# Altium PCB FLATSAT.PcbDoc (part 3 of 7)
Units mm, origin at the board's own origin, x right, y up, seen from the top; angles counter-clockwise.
Board outline 430 x 350 mm, 5 copper layers (Top Layer, Internal Plane 1, Internal Plane 2, DELETEME, Bottom Layer); 808 components, 852 nets, 6407 pads, 939 vias.
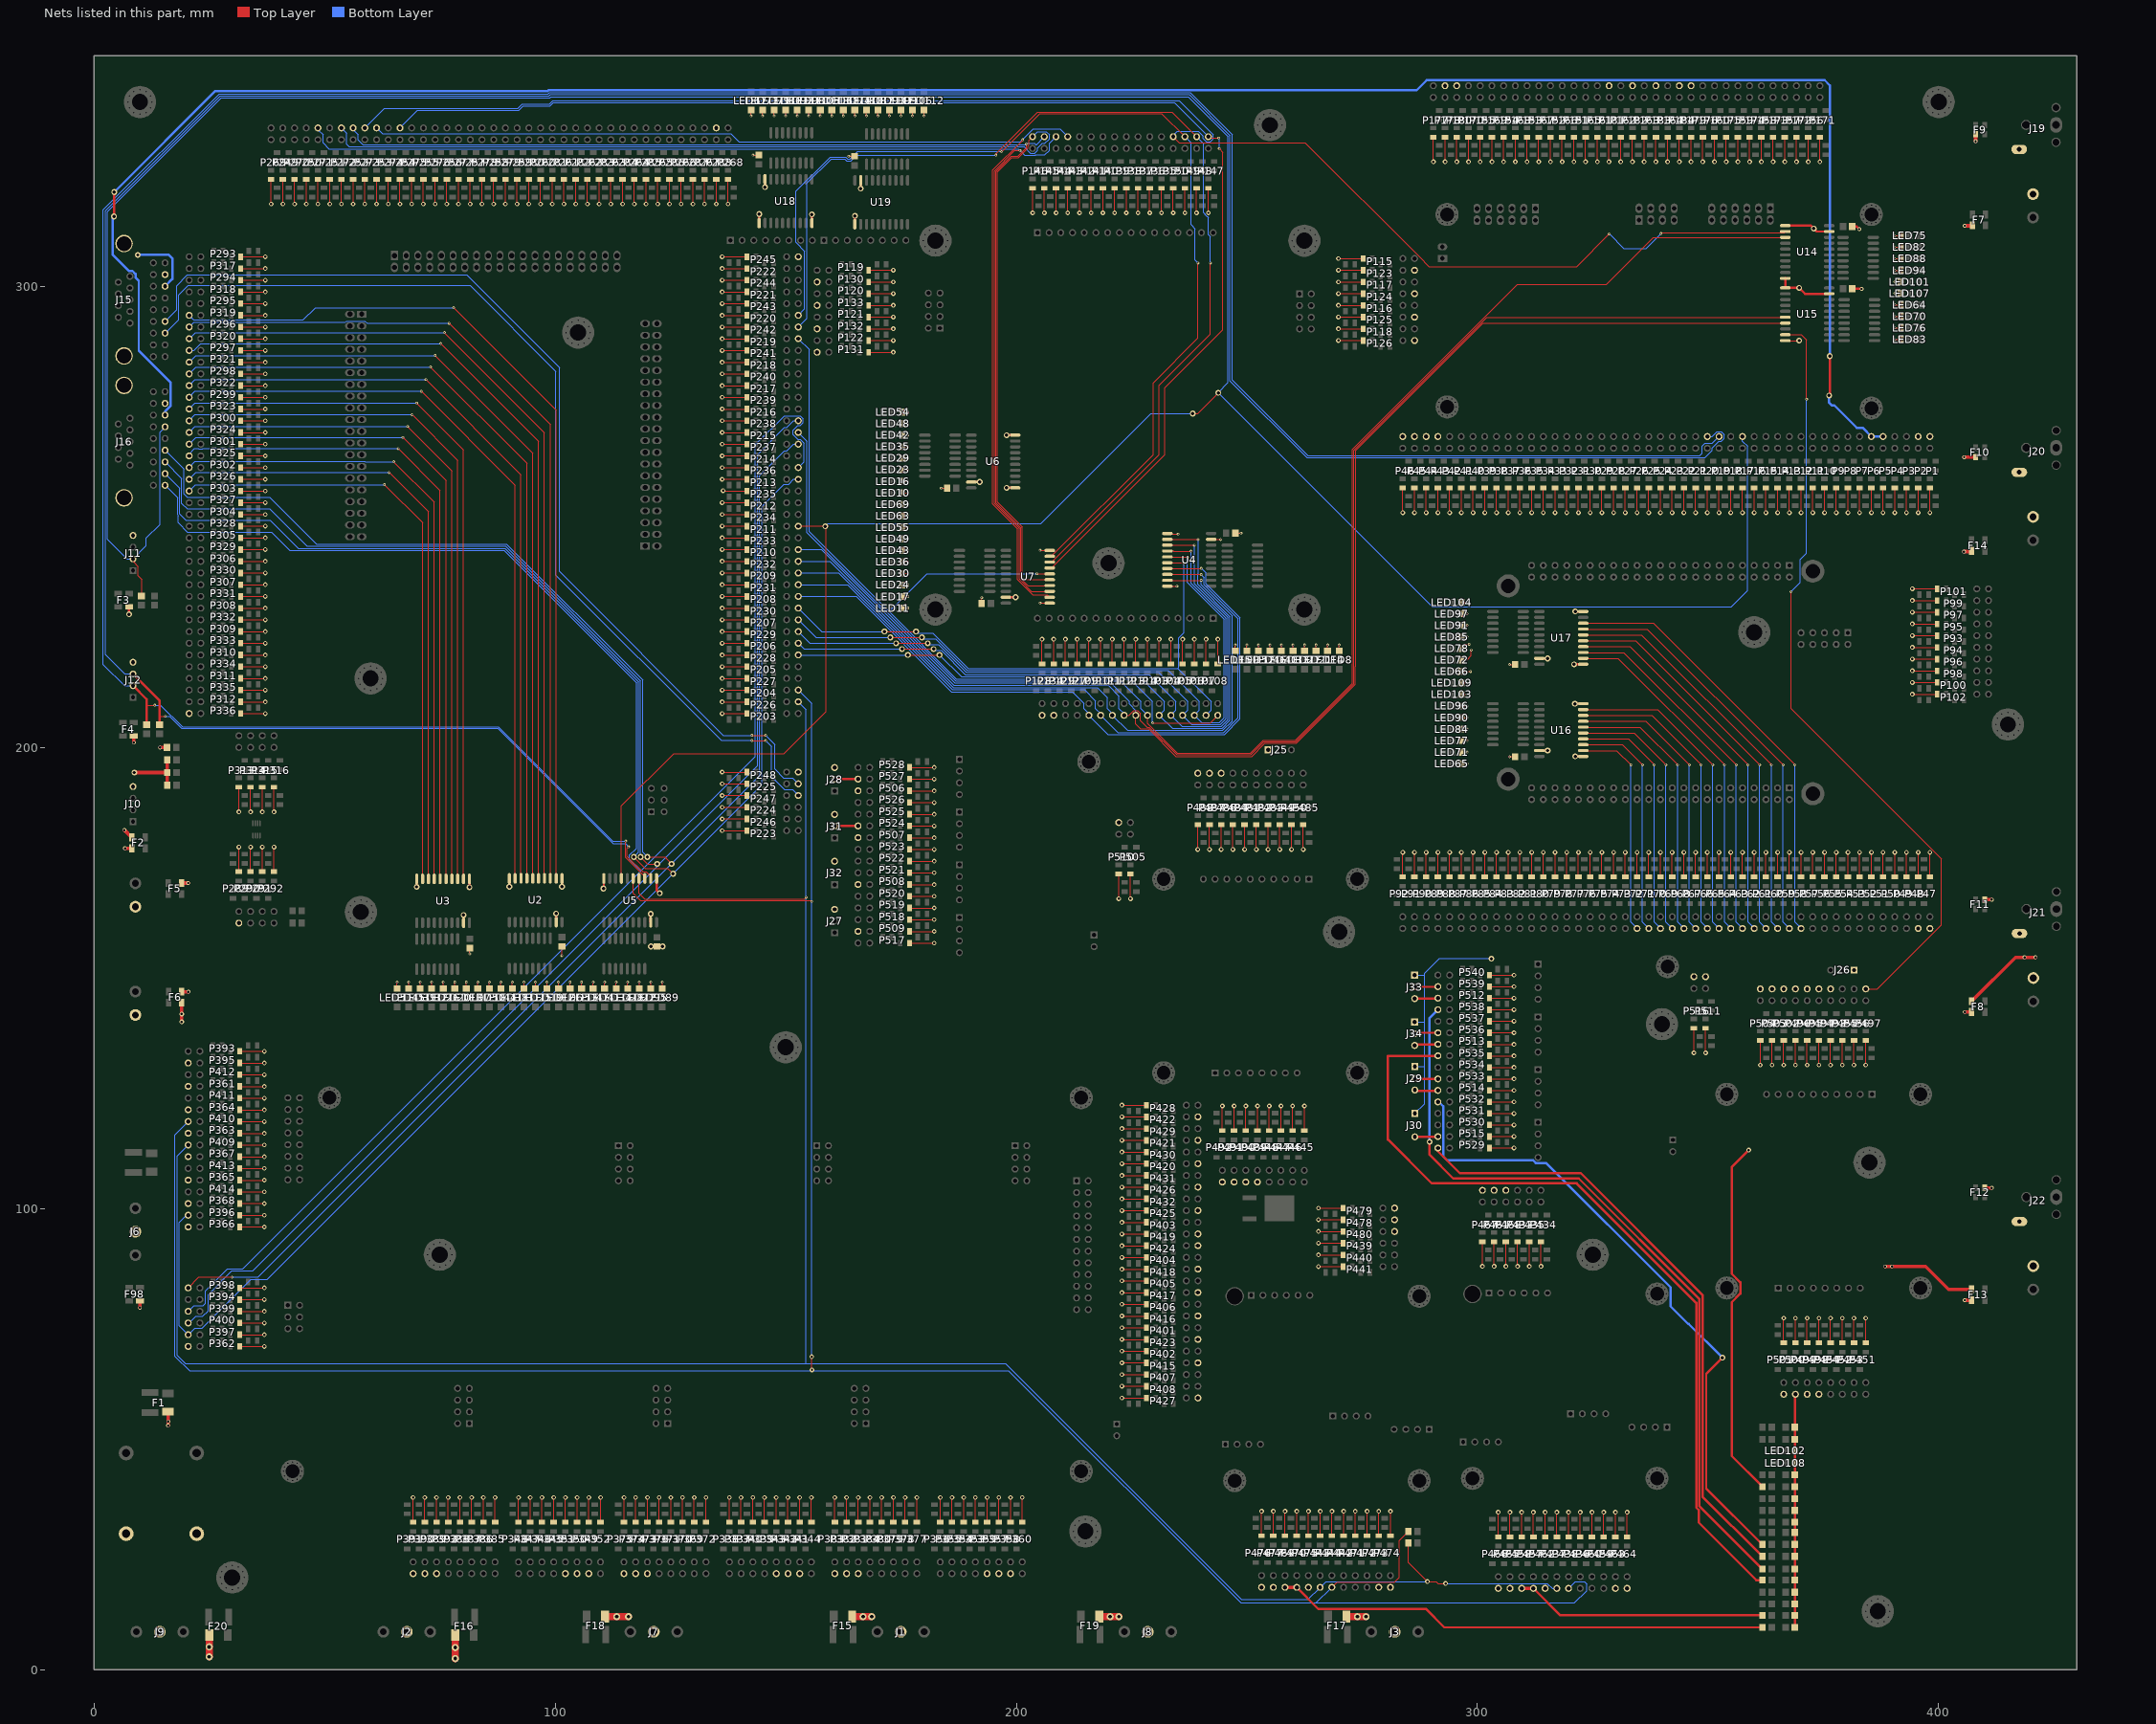
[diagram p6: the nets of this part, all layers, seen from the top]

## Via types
v1: diameter 1.016, hole 0.508, Top Layer to Bottom Layer, 541 vias
v2: diameter 0.6, hole 0.3, Top Layer to Bottom Layer, 214 vias
v3: diameter 1.27, hole 0.711, Top Layer to Bottom Layer, 147 vias
v4: diameter 0.8, hole 0.5, Top Layer to Bottom Layer, 31 vias
v5: diameter 0.5, hole 0.3, Top Layer to Bottom Layer, tented bottom, 5 vias
v6: diameter 1.27, hole 0.635, Top Layer to Bottom Layer, tented both sides, 1 vias

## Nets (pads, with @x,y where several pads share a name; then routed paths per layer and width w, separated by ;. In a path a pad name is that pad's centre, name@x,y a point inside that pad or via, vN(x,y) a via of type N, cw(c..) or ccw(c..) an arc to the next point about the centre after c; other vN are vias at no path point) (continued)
5V0_AUX: F6.1 P535.1 R23.2 | length 181.5
  Top Layer w0.508: P535.1@291.418,133.14 280.603,133.14 280.603,114.985 290.103,105.485 321.503,105.485 347.431,79.557 347.431,35.167 347.946,34.653 347.946,31.942 360.443,19.445 R23.2@361.803,19.445
  Top Layer w0.762: v1(19.049,140.507) v1(19.049,142.21) F6.1@19.049,144.686
5V0_AUX_E\N\: J34.2 P536.1 | length 5
  Top Layer w0.508: J34.2@286.458,138.14 P536.1@291.418,138.14
5V0_BBONE: P5.1 P6.1 P199.1 P538.1 R22.2 | length 689.1
  Top Layer w0.508: v3(4.369,315.189) 4.42,315.239 v3(4.42,320.472) ; v3(289.603,114.485) 289.603,111.685 294.742,106.546 321.942,106.546 348.117,80.371 348.117,35.451 361.703,21.865 R22.2@361.803,21.865 ; v3(376.224,276.352) 376.378,276.505 v3@376.378,284.886 ; v3(376.403,284.886) v3@376.403,285.096
  Bottom Layer w0.508: v3(4.369,315.189) 4.1,314.92 4.1,306.85 7.564,303.386 8.326,303.386 9.026,302.686 9.026,301.924 9.728,301.222 9.728,286.072 16.65,279.15 16.65,274.136 15.443,272.928 P199.1@15.443,272.096 ; v3(4.42,320.472) 26.326,342.378 98.346,342.378 98.545,342.577 286.814,342.577 288.974,344.737 375.277,344.737 376.4,343.614 376.4,287.3 ; v3(289.603,114.485) 289.603,141.325 P538.1@291.418,143.14 ; v3(376.224,276.352) 376.174,276.302 376.174,274.858 376.814,274.218 377.353,274.218 382.229,269.342 383.501,269.342 P6.1@385.398,267.445 P5.1@387.938,267.445 ; v3(376.403,284.886) v3@376.403,285.096 ; v3(376.403,284.886) 376.403,287.25
5V0_BCR: P395.1 P532.1 R20.2 | length 140.5
  Top Layer w0.508: v3(353.103,67.685) 349.603,64.185 349.603,39.285 361.703,27.185 R20.2@361.803,27.185
  Bottom Layer w0.508: P532.1@291.418,123.14 291.648,123.14 292.603,122.185 292.603,111.285 293.403,110.485 312.08,110.485 312.654,109.91 314.878,109.91 341.859,82.929 341.859,78.829 345.703,74.985 345.803,74.985 v3(353.103,67.685)
5V0_TELEM: F2.1 P190.1 P529.1 R9.1 R10.1 R11.1 R21.2 | length 162.5
  Top Layer w0.508: P529.1@291.418,113.14 291.418,112.462 296.203,107.677 322.411,107.677 348.803,81.285 348.803,37.505 361.703,24.605 R21.2@361.803,24.605
  Top Layer w0.762: v4(6.6,182.1) 8.2,180.5 F2.1@8.25,180.5 ; v3(8.778,194.579) R10.1@15.904,194.579 ; R9.1@15.904,191.829 R10.1@15.904,194.579 ; R11.1@15.904,197.329 R10.1@15.904,194.579
  Bottom Layer w0.508: v3(9.525,306.832) 16.256,306.832 17.018,306.07 17.018,301.611 P190.1@15.443,300.036
5V0_UNREG: J29.1 J30.1 J33.1 J34.1 P493.1 P494.1 P495.1 P496.1 P511.1 R15.2 | length 132.5
  Top Layer w0.508: v1(358.803,112.685) 355.103,108.985 355.103,85.889 356.991,84.001 356.991,81.572 355.103,79.684 355.103,46.385 R15.2@361.803,39.685
  Bottom Layer w0.254: J34.1@286.389,140.47 288.488,140.47 288.503,140.485 ; J33.1@286.389,150.63 288.503,150.63 ; J30.1@286.418,120.64 288.503,122.725 288.503,130.8 ; J29.1@286.418,130.8 288.503,130.8 ; v3(303.022,154.178) 303.022,154.305 291.719,154.305 288.503,151.089 288.503,150.63 ; 288.503,130.8 288.503,140.485 ; 288.503,140.485 288.503,150.63
5V0_UNREG_PG: P497.1 U15.9 | length 169.2
  Top Layer w0.152: U15.9@366.75,289.52 370.23,289.52 371.35,288.4 v2(371.35,275.55) ; v2@367.975,233.925 v2(367.975,233.8) 367.975,208.425 398.363,178.037 398.414,178.037 400.6,175.851 400.6,161.55 386.702,147.652 P497.1@384.184,147.652
  Bottom Layer w0.152: v2(367.975,233.8) 369.944,235.769 369.944,240.782 371.35,242.188 v2(371.35,275.55)
8V0_RX1: F8.1 P457.1 P458.1 R24.2 | length 72.4
  Top Layer w0.508: P457.1@312.127,17.64 317.981,11.785 R24.2@361.803,11.785
  Top Layer w0.762: P458.1@309.587,17.64 P457.1@312.127,17.64 ; F8.1@407.15,145 416.65,154.5 v4(421,154.5)
  other v4: 418.6,154.5
8V0_RX2: F13.1 P469.1 P470.1 R26.2 | length 128
  Top Layer w0.508: P470.1@260.811,17.874 265.5,13.185 266.559,13.185 266.576,13.202 288.786,13.202 292.803,9.185 361.783,9.185 R26.2@361.803,9.165
  Top Layer w0.762: P469.1@258.271,17.874 P470.1@260.811,17.874 ; v4(388.374,87.472) v4(389.882,87.472) 397.182,87.472 402.154,82.5 F13.1@407.15,82.5
AFSK1_DET: P108.1 P219.1 U7.6 | length 190.2
  Top Layer w0.152: v2(204.475,237.675) 204.48,237.67 U7.6@207.25,237.67
  Top Layer w0.254: v2(229.575,205.35) 242.048,205.35 P108.1@243.69,206.992
  Bottom Layer w0.152: 172.425,229.5 180.6,237.675 v2(204.475,237.675)
  Bottom Layer w0.254: P219.1@152.734,288.654 155.104,286.284 155.104,246.822 172.425,229.5 187.029,214.896 224.614,214.896 229.531,209.98 229.531,205.394 v2(229.575,205.35)
AFSK1_M0: P144.1 P271.1 U7.3 | length 272.2
  Top Layer w0.152: v2(200.8,329.5) 199.666,329.5 195.24,325.074 195.24,252.926 200.64,247.526 200.64,236.526 200.736,236.43 200.833,236.333 203.306,233.86 U7.3@207.25,233.86
  Bottom Layer w0.254: P271.1@48.594,334.374 48.594,333.994 49.674,332.914 49.674,331.146 50.981,329.839 200.461,329.839 v2(200.8,329.5) 201.858,328.441 204.158,328.441 204.24,328.524 206.206,328.524 207.163,329.481 207.163,331.008 P144.1@208.622,332.468
AFSK1_M1: P145.1 P252.1 U7.4 | length 260.7
  Top Layer w0.152: 201.067,236.567 202.503,235.13 U7.4@207.25,235.13 ; 201.067,236.567 200.97,236.663 200.97,247.663 195.57,253.063 195.57,324.937 198.863,328.23 200.33,328.23 202.2,330.1 v2(202.2,330.9)
  Bottom Layer w0.254: P252.1@56.214,334.374 56.214,333.994 57.294,332.914 57.294,331.766 58.307,330.754 202.054,330.754 202.308,331.008 203.99,331.008 204.244,330.754 204.368,330.754 P145.1@206.082,332.468 P145.1@205.569,332.468
AFSK1_RXD: P143.1 P253.1 U7.2 | length 261.8
  Top Layer w0.152: v2(201.4,331.8) 201.4,331.701 194.909,325.21 194.909,252.79 200.309,247.39 200.309,236.39 200.406,236.293 200.503,236.196 200.6,236.1 203.591,233.108 206.732,233.108 U7.2@207.25,232.59
  Bottom Layer w0.254: P253.1@61.294,334.374 62.56,333.108 138.137,333.108 139.915,331.33 200.876,331.33 203.67,334.124 209.507,334.124 P143.1@211.162,332.468
AFSK1_TXD: P146.1 P272.1 U7.5 | length 272.1
  Top Layer w0.152: P146.1@203.542,332.468 202.754,331.68 202.754,330.671 202.53,330.447 202.53,329.963 200.467,327.9 199,327.9 195.9,324.8 195.9,253.2 201.3,247.8 201.3,236.8 201.7,236.4 U7.5@207.25,236.4
  Bottom Layer w0.254: P272.1@53.674,334.374 54.825,333.223 54.825,330.822 55.35,330.297 201.682,330.297 203.106,328.873 203.979,328.873 204.061,328.955 204.097,328.955 204.623,329.481 204.623,329.998 205.701,331.076 206.218,331.076 207.163,332.021 207.163,332.916 206.53,333.548 204.623,333.548 P146.1@203.542,332.468
AFSK2_DET: P114.1 P215.1 U14.3 | length 332.4
  Top Layer w0.152: P114.1@228.45,206.992 228.45,205.205 234.9,198.755 250.78,198.755 253.599,201.574 260.502,201.574 272.87,213.942 272.87,264.611 308.716,300.457 327.924,300.457 338.107,310.64 U14.3@366.75,310.64
  Bottom Layer w0.254: P215.1@152.734,268.334 154.647,266.421 154.647,246.632 186.84,214.439 222.531,214.439 226.991,209.98 226.991,208.452 P114.1@228.45,206.992
AFSK2_M0: P148.1 P242.1 U7.8 | length 233.8
  Top Layer w0.152: v2(195.6,328.5) 195.6,328.8 204.63,337.83 233.74,337.83 P148.1@239.102,332.468 ; U7.8@207.25,240.21 207.634,240.21 230.97,263.546 230.97,278.566 242.092,289.688 v2(242.092,305.1)
  Bottom Layer w0.152: P148.1@239.102,332.468 240.638,330.932 240.638,315.961 240.88,315.719 240.88,315.642 241.327,315.196 241.403,315.196 241.681,314.919 241.681,311.242 242.092,310.83 v2(242.092,305.1)
  Bottom Layer w0.254: P242.1@152.734,291.194 154.596,293.056 154.596,322.389 159.867,327.66 162.804,327.66 163.251,327.213 164.109,327.213 165.396,328.5 v2(195.6,328.5)
AFSK2_M1: P149.1 P220.1 U7.9 | length 227.9
  Top Layer w0.152: v2(196.8,329.2) 205.1,337.5 231.531,337.5 P149.1@236.562,332.468 ; U7.9@207.25,241.48 207.634,241.48 229.7,263.546 229.7,279.092 239.4,288.792 v2(239.4,305.1)
  Bottom Layer w0.152: P149.1@236.562,332.468 237.9,331.131 237.9,313.37 238.8,312.47 238.8,305.7 v2(239.4,305.1)
  Bottom Layer w0.254: P220.1@152.734,293.734 154.139,295.139 154.139,307.61 152.185,309.563 152.185,320.625 159.652,328.092 162.983,328.092 163.429,327.645 163.931,327.645 165.56,329.275 v2@196.875,329.275
AFSK2_RXD: P147.1 P254.1 U7.7 | length 292.4
  Top Layer w0.152: U7.7@207.25,238.94 207.634,238.94 232.24,263.546 232.24,278.04 244.785,290.585 244.785,329.115 v2(244,329.9) ; P147.1@241.642,332.468 241.911,332.2 v2(243.9,332.2)
  Bottom Layer w0.152: v2(243.9,332.2) 244,332.1 v2(244,329.9)
  Bottom Layer w0.254: P254.1@66.374,334.374 70.197,338.197 92.149,338.197 93.079,339.127 98.939,339.127 99.671,339.859 234.252,339.859 P147.1@241.642,332.468
AFSK2_TXD: P150.1 P273.1 U14.2 | length 351.3
  Top Layer w0.152: P150.1@234.022,332.468 235.316,331.175 262.659,331.175 287.366,306.468 287.366,306.434 289.475,304.325 321.5,304.325 v2(328.575,311.4) ; v2(339.8,311.475) 340,311.675 366.515,311.675 U14.2@366.75,311.91
  Bottom Layer w0.152: v2(328.575,311.4) 331.7,308.275 336.6,308.275 v2(339.8,311.475)
  Bottom Layer w0.254: P273.1@58.754,334.374 63.035,338.655 91.96,338.655 92.89,339.585 98.786,339.585 99.492,340.291 235.347,340.291 242.723,332.916 242.723,332.021 242.09,331.388 241.195,331.388 240.499,332.084 240.499,332.6 239.483,333.616 234.911,333.616 234.022,332.727 P150.1@234.022,332.468
BB_DEBUG_0: P72.1 U16.2 | length 47.8
  Top Layer w0.152: U16.2@322.75,199.34 330.16,199.34 v2(333.25,196.25)
  Bottom Layer w0.152: v2(333.25,196.25) 333.25,162.113 P72.1@334.598,160.765
BB_DEBUG_1: P71.1 U16.3 | length 50.9
  Top Layer w0.152: U16.3@322.75,200.61 331.43,200.61 v2(335.79,196.25)
  Bottom Layer w0.152: v2(335.79,196.25) 335.79,162.113 P71.1@337.138,160.765
BB_DEBUG_2: P70.1 U16.4 | length 54
  Top Layer w0.152: U16.4@322.75,201.88 332.7,201.88 v2(338.33,196.25)
  Bottom Layer w0.152: v2(338.33,196.25) 338.33,162.113 P70.1@339.678,160.765
BB_DEBUG_3: P69.1 U16.5 | length 57
  Top Layer w0.152: U16.5@322.75,203.15 333.97,203.15 v2(340.87,196.25)
  Bottom Layer w0.152: v2(340.87,196.25) 340.87,162.113 P69.1@342.218,160.765
BB_DEBUG_4: P68.1 U16.6 | length 60.1
  Top Layer w0.152: U16.6@322.75,204.42 335.24,204.42 v2(343.41,196.25)
  Bottom Layer w0.152: v2(343.41,196.25) 343.41,162.113 P68.1@344.758,160.765
BB_DEBUG_5: P67.1 U16.7 | length 63.2
  Top Layer w0.152: U16.7@322.75,205.69 336.51,205.69 v2(345.95,196.25)
  Bottom Layer w0.152: v2(345.95,196.25) 345.95,162.113 P67.1@347.298,160.765
BB_DEBUG_6: P66.1 U16.8 | length 66.2
  Top Layer w0.152: U16.8@322.75,206.96 337.78,206.96 v2(348.49,196.25)
  Bottom Layer w0.152: v2(348.49,196.25) 348.49,162.113 P66.1@349.838,160.765
BB_DEBUG_7: P65.1 U16.9 | length 69.3
  Top Layer w0.152: U16.9@322.75,208.23 339.05,208.23 v2(351.03,196.25)
  Bottom Layer w0.152: v2(351.03,196.25) 351.03,162.113 P65.1@352.378,160.765
BB_DEBUG_8: P64.1 U17.2 | length 76.4
  Top Layer w0.152: U17.2@322.75,219.34 330.48,219.34 v2(353.57,196.25)
  Bottom Layer w0.152: v2(353.57,196.25) 353.57,162.113 P64.1@354.918,160.765
BB_DEBUG_9: P63.1 U17.3 | length 79.5
  Top Layer w0.152: U17.3@322.75,220.61 331.75,220.61 v2(356.11,196.25)
  Bottom Layer w0.152: v2(356.11,196.25) 356.11,162.113 P63.1@357.458,160.765
BB_DEBUG_10: P62.1 U17.4 | length 82.6
  Top Layer w0.152: U17.4@322.75,221.88 333.02,221.88 v2(358.65,196.25)
  Bottom Layer w0.152: v2(358.65,196.25) 358.65,162.113 P62.1@359.998,160.765
BB_DEBUG_11: P61.1 U17.5 | length 85.6
  Top Layer w0.152: U17.5@322.75,223.15 334.29,223.15 v2(361.19,196.25)
  Bottom Layer w0.152: v2(361.19,196.25) 361.19,162.113 P61.1@362.538,160.765
BB_DEBUG_12: P60.1 U17.6 | length 88.7
  Top Layer w0.152: U17.6@322.75,224.42 335.56,224.42 v2(363.73,196.25)
  Bottom Layer w0.152: v2(363.73,196.25) 363.73,162.113 P60.1@365.078,160.765
BB_DEBUG_13: P59.1 U17.7 | length 91.8
  Top Layer w0.152: U17.7@322.75,225.69 336.83,225.69 v2(366.27,196.25)
  Bottom Layer w0.152: v2(366.27,196.25) 366.27,162.113 P59.1@367.618,160.765
BB_DEBUG_14: P58.1 U17.8 | length 94.8
  Top Layer w0.152: U17.8@322.75,226.96 338.1,226.96 v2(368.81,196.25)
  Bottom Layer w0.152: v2(368.81,196.25) 368.81,162.113 P58.1@370.158,160.765
BBONE_E\N\: J33.2 P539.1 | length 5
  Top Layer w0.508: J33.2@286.418,148.1 P539.1@291.378,148.1
BBONE_I2C2_SCL: J12.2 P19.1 R2.2 U5.3 | length 669.8
  Top Layer w0.152: 11.43,209.169 v2(13.208,209.169) ; v2(115.316,179.705) 115.316,176.131 119.463,171.984 U5.3@119.463,171.6
  Top Layer w0.508: J12.2@8.5,213.42 11.43,210.49 11.43,209.169 R2.2@11.43,204.962
  Bottom Layer w0.152: v2(13.208,209.169) 14.478,209.169 19.177,204.47 87.716,204.47 112.481,179.705 v2(115.316,179.705)
  Bottom Layer w0.254: J12.2@8.5,213.42 6.629,213.42 2.032,218.017 2.032,316.595 27.205,341.768 98.526,341.768 98.776,342.018 237.721,342.018 246.812,332.927 246.812,279.679 263.195,263.296 348.183,263.296 348.758,263.871 348.758,265.352 349.391,265.985 350.872,265.985 352.332,267.445 P19.1@352.378,267.445
BBONE_I2C2_SDA: J12.3 P20.1 R1.2 U5.2 | length 672.9
  Top Layer w0.152: 14.224,206.756 v2(15.494,206.756) ; v2(115.951,178.486) 115.646,178.181 115.646,176.416 118.98,173.082 119.78,173.082 120.733,172.129 U5.2@120.733,171.6
  Top Layer w0.508: J12.3@8.5,215.96 14.224,210.236 14.224,206.756 R1.2@14.224,204.962
  Bottom Layer w0.152: v2(15.494,206.756) 16.424,206.756 19.04,204.14 87.579,204.14 112.568,179.151 115.286,179.151 v2(115.951,178.486)
  Bottom Layer w0.254: J12.3@8.5,215.96 6.629,215.96 2.489,220.1 2.489,316.406 27.42,341.336 98.705,341.336 98.955,341.586 237.506,341.586 246.355,332.738 246.355,279.49 263.005,262.839 349.3,262.839 350.918,264.458 350.918,264.973 352.31,266.365 352.825,266.365 353.458,266.998 353.458,267.892 352.825,268.525 351.931,268.525 350.85,267.445 P20.1@349.838,267.445
BCR_E\N\: J29.2 P533.1 | length 5
  Top Layer w0.508: J29.2@286.418,128.1 P533.1@291.378,128.1
BCR_MISO: P196.1 P237.1 P398.1 | length 418.2
  Top Layer w0.254: P398.1@20.451,82.812 22.763,85.125 v2(29.95,85.125) ; v3(120.015,176.251) 123.749,176.251 v3(125.24,174.76)
  Bottom Layer w0.254: P196.1@15.443,264.476 19.5,260.418 19.5,255 20.25,254.25 38.125,254.25 48.256,244.119 89.494,244.119 118.999,214.614 118.999,177.267 v3(120.015,176.251) ; v2@29.925,85.16 35.64,85.16 v3(125.24,174.76) 144.352,193.872 144.352,258.94 149.747,264.334 150.298,264.334 151.758,265.794 P237.1@152.734,265.794
BCR_MOSI: P197.1 P238.1 P400.1 | length 423.2
  Top Layer w0.254: v3(118.542,176.251) 120.04,174.752 v3(122.149,174.752)
  Bottom Layer w0.254: P197.1@15.443,261.936 19.049,258.329 19.049,252.951 20.25,251.75 38.088,251.75 46.176,243.662 89.304,243.662 118.542,214.425 v3(118.542,176.251) ; P400.1@20.451,75.192 20.717,75.192 22.15,76.625 23.575,76.625 24.781,77.831 24.781,81.353 29.904,86.475 34.466,86.475 122.149,174.158 v3@122.149,174.333 ; v3(122.149,174.752) 122.567,174.752 143.895,196.079 143.895,263.562 149.747,269.414 150.298,269.414 151.758,270.874 P238.1@152.734,270.874
BCR_R\S\T\: P194.1 P213.1 P396.1 P397.1 | length 445.3
  Top Layer w0.254: v3(117.069,176.251) 119.534,173.785 124.459,173.785 v3(125.602,172.642)
  Bottom Layer w0.254: P194.1@15.443,259.396 18.618,256.221 18.568,256.221 18.568,250.682 20,249.25 38.25,249.25 44.295,243.205 89.115,243.205 118.085,214.235 118.085,177.267 v3(117.069,176.251) ; P396.1@20.451,98.56 20.084,98.56 18.52,96.996 18.52,74.583 P397.1@20.451,72.652 21.911,74.112 23.438,74.112 34.029,84.703 37.598,84.703 144.86,191.965 144.86,252.292 149.662,257.094 150.641,257.094 151.722,258.174 P213.1@152.734,258.174
BCR_SCK: P195.1 P236.1 P399.1 | length 434.4
  Bottom Layer w0.254: P195.1@15.443,256.856 18.136,254.162 18.136,250.389 18.25,250.276 18.25,248.75 20.25,246.75 38.5,246.75 42.502,242.748 88.925,242.748 117.627,214.046 117.627,178.174 116.103,176.65 116.103,175.747 118.625,173.225 ; P399.1@20.451,77.732 21.668,78.95 23.7,78.95 24.225,79.475 24.225,82.132 29,86.907 32.307,86.907 118.625,173.225 ; 150.045,271.955 150.044,271.954 149.747,271.954 143.438,265.645 143.438,198.038 118.625,173.225 ; 150.046,271.954 153.181,271.954 153.814,271.321 153.814,270.427 153.181,269.794 152.666,269.794 151.654,268.781 151.654,267.887 152.666,266.874 153.181,266.874 154.004,266.052 154.004,261.984 P236.1@152.734,260.714
COMMS_E\N\: J28.2 P527.1 | length 5.1
  Top Layer w0.508: J28.2@160.608,193.15 P527.1@165.688,193.15
CSC_E\N\: J31.2 P524.1 | length 5.1
  Top Layer w0.508: J31.2@160.608,182.99 P524.1@165.688,182.99
CSC_ISP: P188.1 P247.1 | length 220.3
  Top Layer w0.254: v2@142.689,201.51 v2(145.669,201.51)
  Bottom Layer w0.254: P188.1@15.443,289.876 18.386,292.819 18.386,298.136 20.5,300.25 81.532,300.25 100.185,281.597 100.185,237.381 136.039,201.527 v2(142.672,201.527) ; v2(145.669,201.51) 146.939,200.24 146.939,193.65 149.733,190.856 151.472,190.856 P247.1@152.734,189.594
CSC_RST: P187.1 P225.1 | length 219.3
  Top Layer w0.254: v2(142.672,202.659) v2@145.652,202.659
  Bottom Layer w0.254: P187.1@15.443,292.416 17.955,294.928 17.955,300.146 20.308,302.5 80.882,302.5 100.985,282.397 100.985,238.181 136.508,202.659 v2(142.672,202.659) ; v2(145.669,202.641) 147.625,200.685 147.625,195.326 149.555,193.396 151.472,193.396 P225.1@152.734,192.134
DEBUG_0: P303.1 U3.9 | length 131.8
  Top Layer w0.152: v2(63,257) 71.27,248.73 U3.9@71.27,171.5
  Bottom Layer w0.254: P303.1@20.654,255.634 22.02,257 v2(63,257)
DEBUG_1: P326.1 U3.8 | length 135.7
  Top Layer w0.152: v2(64,259.659) 72.54,251.119 U3.8@72.54,171.5
  Bottom Layer w0.254: P326.1@20.654,258.174 22.139,259.659 v2(64,259.659)
DEBUG_2: P302.1 U3.7 | length 139
  Top Layer w0.152: v2(65,262) 73.81,253.19 U3.7@73.81,171.5
  Bottom Layer w0.254: P302.1@20.654,260.714 21.959,262.019 58.801,262.019 58.819,262 v2(65,262)
DEBUG_3: P325.1 U3.6 | length 143.4
  Top Layer w0.152: v2@66,264.825 75.08,255.745 U3.6@75.08,171.5
  Bottom Layer w0.254: P325.1@20.654,263.254 20.654,263.654 21.825,264.825 22.671,264.825 22.757,264.739 23.631,264.739 23.717,264.825 v2(66,264.825)
DEBUG_4: P301.1 U3.5 | length 146.6
  Top Layer w0.152: v2(67,267.25) 76.35,257.9 U3.5@76.35,171.5
  Bottom Layer w0.254: P301.1@20.654,265.794 22.11,267.25 v2(67,267.25)
DEBUG_5: P324.1 U3.4 | length 150
  Top Layer w0.152: v2(68,269.639) 77.62,260.019 U3.4@77.62,171.5
  Bottom Layer w0.254: P324.1@20.654,268.334 21.959,269.639 v2(68,269.639)
DEBUG_6: P300.1 U3.3 | length 153.7
  Top Layer w0.152: v2(69,272.179) 78.89,262.289 U3.3@78.89,171.5
  Bottom Layer w0.254: P300.1@20.654,270.874 21.959,272.179 v2(69,272.179)
DEBUG_7: P323.1 U3.2 | length 157.3
  Top Layer w0.152: v2(70,274.719) 80.16,264.559 U3.2@80.16,171.5
  Bottom Layer w0.254: P323.1@20.654,273.414 21.959,274.719 v2(70,274.719)
DEBUG_8: P299.1 U2.9 | length 164.9
  Top Layer w0.152: v2(71,277.259) 91.345,256.914 U2.9@91.345,171.625
  Bottom Layer w0.254: P299.1@20.654,275.954 21.959,277.259 v2(71,277.259)
DEBUG_9: P322.1 U2.8 | length 168.6
  Top Layer w0.152: v2(72,279.799) 92.615,259.184 U2.8@92.615,171.625
  Bottom Layer w0.254: P322.1@20.654,278.494 21.959,279.799 v2(72,279.799)
DEBUG_10: P298.1 U2.7 | length 172.5
  Top Layer w0.152: v2(73,282.519) 93.885,261.634 U2.7@93.885,171.625
  Bottom Layer w0.254: P298.1@20.654,281.034 22.139,282.519 v2(73,282.519)
DEBUG_11: P321.1 U2.6 | length 176.1
  Top Layer w0.152: v2(74,285) 95.155,263.845 U2.6@95.155,171.625
  Bottom Layer w0.254: P321.1@20.654,283.574 22.08,285 v2(74,285)
DEBUG_12: P297.1 U2.5 | length 179.9
  Top Layer w0.152: v2(75.225,287.599) 96.425,266.399 U2.5@96.425,171.625
  Bottom Layer w0.254: P297.1@20.654,286.114 21.702,286.114 23.187,287.599 v2(75.225,287.599)
DEBUG_13: P320.1 U2.4 | length 183.3
  Top Layer w0.152: v2(76,290) 97.695,268.305 U2.4@97.695,171.625
  Bottom Layer w0.254: P320.1@20.654,288.654 22,290 v2(76,290)
DEBUG_14: P296.1 U2.3 | length 186.6
  Top Layer w0.152: v2(77,292) 98.965,270.035 U2.3@98.965,171.625
  Bottom Layer w0.254: P296.1@20.654,291.194 21.709,292.249 54.53,292.249 54.78,292.499 58.801,292.499 59.299,292 v2(77,292)
DEBUG_15: P319.1 U2.2 | length 191.8
  Top Layer w0.152: v2(78,295.375) 100.235,273.14 U2.2@100.235,171.625
  Bottom Layer w0.152: P319.1@20.654,293.734 21.658,292.73 37.738,292.73
  Bottom Layer w0.254: 37.738,292.73 45.38,292.73 48.025,295.375 77.625,295.375 v2(78,295.375)
DTMF1Q1: P103.1 P228.1 U4.2 | length 153.4
  Top Layer w0.254: v3(176.491,220.078) v3(183.349,220.078) v3@183.603,219.824 ; U4.2@232.75,245.16 234.049,245.16 234.109,245.1 v2(239.425,245.1)
  Bottom Layer w0.254: P228.1@152.734,220.074 176.487,220.074 v3(176.491,220.078) ; v3(183.349,220.078) 188.073,215.353 226.697,215.353 232.071,209.98 232.071,208.072 P103.1@230.99,206.992 233.837,204.145 244.613,204.145 246.37,205.902 246.37,228.394 239.418,235.346 239.418,237.636 ; 239.425,237.642 v2(239.425,245.1)
DTMF1Q2: P104.1 P206.1 U4.3 | length 151.3
  Top Layer w0.254: v3(175.221,221.348) v3(182.079,221.348) ; U4.3@232.75,243.89 234.049,243.89 234.064,243.875 v2(238.625,243.875)
  Bottom Layer w0.254: P206.1@152.734,222.614 154,221.348 v3(175.221,221.348) ; v3(182.079,221.348) 182.383,221.043 183.748,221.043 188.981,215.81 228.78,215.81 234.611,209.98 234.611,208.072 P104.1@233.53,206.992 235.945,204.577 244.435,204.577 245.939,206.081 245.939,228.215 238.625,235.529 v2(238.625,243.875)
DTMF1Q3: P105.1 P229.1 U4.4 | length 149.9
  Top Layer w0.254: v3(173.951,222.618) v3(180.809,222.618) ; U4.4@232.75,242.62 234.049,242.62 234.069,242.6 v2(237.9,242.6)
  Bottom Layer w0.254: P229.1@152.734,225.154 155.27,222.618 v3(173.951,222.618) 174.063,222.618 v3@174.235,222.446 ; v3(180.809,222.618) 181.113,222.313 183.125,222.313 189.17,216.268 230.863,216.268 237.151,209.98 237.151,208.072 P105.1@236.07,206.992 238.054,205.009 244.256,205.009 245.507,206.26 245.507,228.036 237.9,235.643 v2(237.9,242.6)
DTMF1Q4: P106.1 P207.1 U4.5 | length 148
  Top Layer w0.254: v3(172.681,223.888) v3(179.539,223.888) ; U4.5@232.75,241.35 237,241.35 v2(237.1,241.25)
  Bottom Layer w0.254: P207.1@152.734,227.694 156.54,223.888 v3(172.681,223.888) v3@172.935,223.888 ; v3(179.539,223.888) 179.843,223.583 182.502,223.583 189.36,216.725 232.945,216.725 239.691,209.98 239.691,208.072 P106.1@238.61,206.992 240.162,205.441 244.077,205.441 245.075,206.439 245.075,227.857 237.1,235.832 v2(237.1,241.25)
DTMF1ST: P107.1 P230.1 U4.6 | length 128.5
  Top Layer w0.254: v3(171.411,225.158) v3(178.269,225.158) ; U4.6@232.75,240.08 236.17,240.08 v2(236.325,239.925)
  Bottom Layer w0.254: P230.1@152.734,230.234 157.81,225.158 v3(171.411,225.158) v3@171.665,225.158 ; v3(178.269,225.158) 178.573,224.853 181.878,224.853 189.549,217.182 235.028,217.182 ; v2(236.325,239.925) 236.325,224.873 235.767,224.315 235.734,224.315 235.2,223.781 235.2,217.354 235.028,217.182 ; P107.1@241.15,206.992 242.231,208.072 242.231,209.98 235.028,217.182
DTMF2Q1: P109.1 P208.1 U4.7 | length 153.9
  Top Layer w0.254: U4.7@232.75,238.81 240.06,238.81 v2(240.1,238.85)
  Bottom Layer w0.254: P208.1@152.734,232.774 165.272,232.774 185.944,212.102 212.168,212.102 214.67,209.6 214.67,208.452 215.75,207.372 P109.1@215.75,206.992 219.893,202.85 245.15,202.85 248.537,206.237 248.537,228.138 241.175,235.5 241.175,237.875 v2@240.2,238.85
DTMF2Q2: P110.1 P231.1 U4.8 | length 152.9
  Top Layer w0.254: U4.8@232.75,237.54 240.06,237.54 v2(240.1,237.5)
  Bottom Layer w0.254: P231.1@152.734,235.314 163.379,235.314 186.133,212.559 214.743,212.559 217.21,210.092 217.21,208.452 218.29,207.372 P110.1@218.29,206.992 222.001,203.282 244.971,203.282 248.105,206.415 248.105,227.881 240.743,235.242 240.743,236.857 v2(240.1,237.5)
DTMF2Q3: P111.1 P209.1 U4.9 | length 151.4
  Top Layer w0.254: U4.9@232.75,236.27 234.049,236.27 234.054,236.275 v2(240.1,236.275)
  Bottom Layer w0.254: P209.1@152.734,237.854 161.485,237.854 186.323,213.016 217.588,213.016 219.75,210.854 219.75,208.452 220.83,207.372 P111.1@220.83,206.992 224.109,203.714 244.792,203.714 246.802,205.724 246.802,228.573 240.1,235.275 240.1,236.1 240.188,236.188 v2@240.275,236.275
DTMF2Q4: P112.1 P232.1 U15.6 | length 304
  Top Layer w0.152: P112.1@223.37,206.992 224.419,206.992 225.474,208.047 226.347,208.047 226.965,207.429 226.965,205.81 228.375,204.4 228.788,204.4 234.763,198.425 250.917,198.425 253.736,201.244 260.639,201.244 273.2,213.805 273.2,264.474 302.056,293.33 U15.6@366.75,293.33
  Bottom Layer w0.254: P232.1@152.734,240.394 159.592,240.394 186.512,213.474 219.925,213.474 222.29,211.108 222.29,208.452 223.37,207.372 P112.1@223.37,206.992
DTMF2ST: P113.1 P210.1 U15.7 | length 303.2
  Top Layer w0.152: P113.1@225.91,206.992 225.91,205.065 226.905,204.07 228.651,204.07 234.627,198.095 251.054,198.095 253.873,200.914 260.776,200.914 273.53,213.668 273.53,217.57 273.632,217.671 273.632,264.439 301.253,292.06 U15.7@366.75,292.06
  Bottom Layer w0.254: P210.1@152.734,242.934 157.698,242.934 186.651,213.982 220.449,213.982 224.497,209.934 224.497,209.41 225.91,207.996 P113.1@225.91,206.992
GND: C1.1 C2.1 C3.1 C4.1 C5.1 C6.1 C7.1 C8.1 C9.1 C10.1 C11.1 C12.1 C13.1 F1.3 F2.3 F3.3 F4.3 F5.3 F6.3 F7.3 F8.3 F9.3 F10.3 F11.3 F12.3 F13.3 F14.3 F15.3 F16.3 F17.3 F18.3 F19.3 F20.3 F98.3 J1.2 J2.2 J3.2 J5.1 J6.2 J7.2 J8.2 J9.2 J10.4 J11.4 J12.4 J13.2 J14.2 J15.10 J15.11 J16.10 J16.11 J17.2 J18.2 J19.1 J20.1 J21.1 J22.1 J23.2 J24.2 J25.1 J26.1 J27.3 J28.3 J29.3 J30.3 J31.3 J32.3 J33.3 J34.3 LED1.2 LED2.2 LED3.2 LED4.2 LED5.2 LED6.1 LED7.1 LED8.1 LED9.1 LED10.1 LED11.1 LED12.1 LED13.1 LED14.1 LED15.1 LED16.1 LED17.1 LED18.2 LED19.1 LED20.1 LED21.1 LED22.1 LED23.1 LED24.1 LED25.1 LED26.1 LED27.1 LED28.1 LED29.1 LED30.1 LED31.1 LED32.1 LED33.1 LED34.1 LED35.1 LED36.1 LED37.2 LED38.1 LED39.1 LED40.1 LED41.1 LED42.1 LED43.1 LED44.1 LED45.1 LED46.1 LED47.1 LED48.1 LED49.1 LED50.1 LED51.1 LED52.1 LED53.1 LED54.1 LED55.1 LED56.2 LED57.2 LED58.2 LED59.2 LED60.2 LED61.2 LED62.2 LED63.1 LED64.1 LED65.1 LED66.1 LED67.1 LED68.1 LED69.1 LED70.1 LED71.1 LED72.1 LED73.1 LED74.1 LED75.1 LED76.1 LED77.1 LED78.1 LED79.1 LED80.1 LED81.2 LED82.1 LED83.1 LED84.1 LED85.1 LED86.1 LED87.1 LED88.1 LED89.1 LED90.1 LED91.1 LED92.1 LED93.1 LED94.1 LED95.1 LED96.1 LED97.1 LED98.1 LED99.1 LED100.2 LED101.1 LED102.1 LED103.1 LED104.1 LED105.1 LED106.1 LED107.1 LED108.1 LED109.1 LED111.1 LED112.1 P1.1 P1.3 P2.1 P2.3 P3.3 P4.3 P5.3 P6.3 P7.3 P8.3 P9.3 P10.3 P11.3 P12.3 P13.3 P14.3 P15.3 P16.3 P17.3 P18.3 P19.3 P20.3 P21.3 P22.3 P23.3 P24.3 P25.3 P26.3 P27.3 P28.3 P29.3 P30.3 P31.3 P32.3 P33.3 P34.3 P35.3 P36.3 P37.3 P38.3 P39.3 P40.3 P41.3 P42.3 P43.1 P43.3 P44.1 P44.3 P45.1 P45.3 P46.1 P46.3 P47.1 P47.3 P48.1 P48.3 P49.3 P50.3 P51.3 P52.3 P53.3 P54.3 P55.3 P56.3 P57.3 P58.3 P59.3 P60.3 P61.3 P62.3 P63.3 P64.3 P65.3 P66.3 P67.3 P68.3 P69.3 P70.3 P71.3 P72.3 P73.3 P74.3 P75.3 P76.3 P77.3 P78.3 P79.3 P80.3 P81.3 P82.3 P83.3 P84.3 P85.3 P86.3 P87.3 P88.3 P89.3 P90.3 P91.3 P92.3 P93.3 P94.3 P95.3 P96.3 P97.3 P98.3 P99.3 P100.3 P101.3 P102.3 P103.3 P104.3 P105.3 P106.3 P107.3 P108.3 P109.3 P110.3 P111.3 P112.3 P113.3 P114.3 P115.3 P116.3 P117.3 P118.3 P119.3 P120.3 P121.3 P122.3 P123.1 P123.3 P124.1 P124.3 P125.1 P125.3 P126.1 P126.3 P127.3 P128.1 P128.3 P129.3 P130.1 P130.3 P131.1 P131.3 P132.1 P132.3 P133.1 P133.3 P134.1 P134.3 P135.3 P136.3 P137.3 P138.3 P139.3 P140.3 P141.3 P142.3 P143.3 P144.3 P145.3 P146.3 P147.3 P148.3 P149.3 P150.3 P151.3 P152.3 P153.3 P154.3 P155.3 P156.3 P157.3 P158.3 P159.3 P160.3 P161.3 P162.3 P163.3 P164.3 P165.3 P166.3 P167.3 P168.3 P169.3 P170.3 P171.3 P172.3 P173.3 P174.3 P175.3 P176.3 P177.3 P178.1 P178.3 P179.1 P179.3 P180.1 P180.3 P181.1 P181.3 P182.1 P182.3 P183.1 P183.3 P184.1 P184.3 P193.1 P202.1 P203.3 P204.3 P205.3 P206.3 P207.3 P208.3 P209.3 P210.3 P211.3 P212.3 P213.3 P214.3 P215.3 P216.3 P217.3 P218.3 P219.3 P220.3 P221.3 P222.3 P223.3 P224.3 P225.3 P226.3 P227.3 P228.3 P229.3 P230.3 P231.3 P232.3 P233.3 P234.3 P235.3 P236.3 P237.3 P238.3 P239.3 P240.3 P241.3 P242.3 P243.3 P244.3 P245.1 P245.3 P246.3 P247.3 P248.1 P248.3 P249.3 P250.3 P251.3 P252.3 P253.3 P254.3 P255.3 P256.3 P257.3 P258.3 P259.3 P260.3 P261.3 P262.3 P263.3 P264.3 P265.3 P266.3 P267.3 P268.3 P269.3 P270.3 P271.3 P272.3 P273.3 P274.3 P275.3 P276.3 P277.3 P278.3 P279.3 P280.3 P281.3 P282.3 P283.3 P284.3 P285.3 P286.3 P287.3 P288.1 P288.3 P289.1 P289.3 P290.3 P291.3 P292.3 P293.3 P294.3 P295.3 P296.3 P297.3 P298.3 P299.3 P300.3 P301.3 P302.3 P303.3 P304.3 P305.3 P306.3 P307.3 P308.3 P309.3 P310.3 P311.3 P312.3 P313.3 P314.3 P315.3 P316.3 P317.3 P318.3 P319.3 P320.3 P321.3 P322.3 P323.3 P324.3 P325.3 P326.3 P327.3 P328.3 P329.3 P330.3 P331.3 P332.3 P333.3 P334.3 P335.3 P336.1 P336.3 P337.3 P338.3 P339.3 P340.3 P341.1 P341.3 P342.1 P342.3 P343.1 P343.3 P344.3 P345.3 P346.3 P347.3 P348.3 P349.1 P349.3 P350.1 P350.3 P351.1 P351.3 P352.3 P353.3 P354.3 P355.3 P356.3 P357.1 P357.3 P358.1 P358.3 P359.1 P359.3 P360.3 P361.1 P361.3 P362.1 P362.3 P363.1 P363.3 P364.1 P364.3 P365.1 P365.3 P366.1 P366.3 P367.1 P367.3 P368.1 P368.3 P369.3 P370.3 P371.3 P372.3 P373.1 P373.3 P374.1 P374.3 P375.1 P375.3 P376.3 P377.3 P378.3 P379.3 P380.3 P381.1 P381.3 P382.1 P382.3 P383.1 P383.3 P384.3 P385.3 P386.3 P387.3 P388.3 P389.1 P389.3 P390.1 P390.3 P391.1 P391.3 P392.3 P393.3 P394.3 P395.3 P396.3 P397.3 P398.3 P399.3 P400.3 P401.3 P402.3 P403.3 P404.3 P405.3 P406.3 P407.3 P408.3 P409.3 P410.3 P411.3 P412.3 P413.3 P414.3 P415.1 P415.3 P416.1 P416.3 P417.1 P417.3 P418.1 P418.3 P419.1 P419.3 P420.1 P420.3 P421.1 P421.3 P422.1 P422.3 P423.1 P423.3 P424.1 P424.3 P425.1 P425.3 P426.1 P426.3 P427.1 P427.3 P428.3 P429.3 P430.3 P431.3 P432.3 P433.3 P434.3 P435.3 P436.3 P437.3 P438.3 P439.3 P440.3 P441.3 P442.3 P443.3 P444.3 P445.3 P446.3 P447.3 P448.3 P449.3 P450.3 P451.3 P452.3 P453.3 P454.3 P455.3 P456.3 P457.3 P458.3 P459.3 P460.3 P461.1 P461.3 P462.1 P462.3 P463.1 P463.3 P464.1 P464.3 P465.1 P465.3 P466.1 P466.3 P467.1 P467.3 P468.1 P468.3 P469.3 P470.3 P471.3 P472.3 P473.1 P473.3 P474.1 P474.3 P475.1 P475.3 P476.1 P476.3 P477.1 P477.3 P478.1 P478.3 P479.1 P479.3 P480.1 P480.3 P481.3 P482.3 P483.3 P484.3 P485.3 P486.1 P486.3 P487.1 P487.3 P488.1 P488.3 P489.1 P489.3 P490.1 P490.3 P491.1 P491.3 P492.1 P492.3 P493.3 P494.3 P495.3 P496.3 P497.3 P498.1 P498.3 P499.1 P499.3 P500.1 P500.3 P501.1 P501.3 P502.1 P502.3 P503.1 P503.3 P504.1 P504.3 P505.3 P506.1 P506.3 P507.1 P507.3 P508.1 P508.3 P509.1 P509.3 P510.1 P510.3 P511.3 P512.1 P512.3 P513.1 P513.3 P514.1 P514.3 P515.1 P515.3 P516.1 P516.3 P517.3 P518.3 P519.3 P520.3 P521.3 P522.3 P523.3 P524.3 P525.3 P526.3 P527.3 P528.3 P529.3 P530.3 P531.3 P532.3 P533.3 P534.3 P535.3 P536.3 P537.3 P538.3 P539.3 P540.3 pad.0 pad.1 U2.1 U2.10 U2.19 U3.1 U3.10 U3.19 U4.1 U4.10 U4.19 U5.1 U5.10 U5.19 U6.1 U6.10 U6.19 U7.1 U7.10 U7.19 U14.1 U14.10 U14.19 U15.1 U15.10 U15.19 U16.1 U16.10 U16.19 U17.1 U17.10 U17.19 U18.1 U18.10 U18.19 U19.1 U19.19 | length 345.1
  Top Layer w0.152: LED51.1@65.75,147.75 v2@65.75,149 ; LED45.1@68.25,147.75 v2@68.25,149 ; LED39.1@70.75,147.75 v2@70.75,149 ; LED32.1@73.25,147.75 v2@73.25,149 ; LED26.1@75.75,147.75 v2@75.75,149 ; LED20.1@78.25,147.75 v2@78.25,149 ; LED13.1@80.75,147.75 v2@80.75,149 ; v2(81.5,155.25) C3.1@81.5,156.5 ; LED7.1@83.25,147.75 v2@83.25,149 ; LED50.1@85.75,147.75 v2@85.75,149 ; LED44.1@88.25,147.75 v2@88.25,149 ; LED38.1@90.75,147.75 v2@90.75,149 ; LED31.1@93.25,147.75 v2@93.25,149 ; LED25.1@95.75,147.75 v2@95.75,149 ; LED19.1@98.25,147.75 v2@98.25,149 ; LED12.1@100.75,147.75 v2@100.75,149 ; v2(101.472,154.862) 101.505,154.895 C2.1@101.505,156.875 ; LED6.1@103.25,147.75 v2@103.25,149 ; LED53.1@105.75,147.75 v2@105.75,149 ; LED47.1@108.25,147.75 v2@108.25,149 ; LED41.1@110.75,147.75 v2@110.75,149 ; LED34.1@113.25,147.75 v2@113.25,149 ; LED28.1@115.75,147.75 v2@115.75,149 ; LED22.1@118.25,147.75 v2@118.25,149 ; LED95.1@120.75,147.75 v2@120.75,149 ; LED89.1@123.25,147.75 v2@123.25,149 ; v2(142.5,337) LED67.1@142.5,338.25 ; v2(142.93,328.5) C12.1@144.18,328.5 ; v2(145,337) LED73.1@145,338.25 ; v2(147.5,337) LED79.1@147.5,338.25 ; v2(150,337) LED86.1@150,338.25 ; v2(152.5,337) LED92.1@152.5,338.25 ; v2(155,337) LED98.1@155,338.25 ; v2(157.5,337) LED105.1@157.5,338.25 ; v2(160,337) LED111.1@160,338.25 ; v2(162.5,337) LED68.1@162.5,338.25 ; v2(163.68,328.25) C13.1@164.93,328.25 ; v2(165,337) LED74.1@165,338.25 ; v2(167.5,337) LED80.1@167.5,338.25 ; v2(170,337) LED87.1@170,338.25 ; v2(172.5,337) LED93.1@172.5,338.25 ; v2(175,337) LED99.1@175,338.25 ; LED11.1@175.25,230.25 v2(176.5,230.25) ; LED17.1@175.25,232.75 v2(176.5,232.75) ; LED24.1@175.25,235.25 v2(176.5,235.25) ; LED30.1@175.25,237.75 v2(176.5,237.75) ; LED36.1@175.25,240.25 v2(176.5,240.25) ; LED43.1@175.25,242.75 v2(176.5,242.75) ; LED49.1@175.25,245.25 v2(176.5,245.25) ; LED55.1@175.25,247.75 v2(176.5,247.75) ; LED63.1@175.25,250.25 v2(176.5,250.25) ; LED69.1@175.25,252.75 v2(176.5,252.75) ; LED10.1@175.25,255.25 v2(176.5,255.25) ; LED16.1@175.25,257.75 v2(176.5,257.75) ; LED23.1@175.25,260.25 v2(176.5,260.25) ; LED29.1@175.25,262.75 v2(176.5,262.75) ; LED35.1@175.25,265.25 v2(176.5,265.25) ; LED42.1@175.25,267.75 v2(176.5,267.75) ; LED48.1@175.25,270.25 v2(176.5,270.25) ; LED54.1@175.25,272.75 v2(176.5,272.75) ; v2(177.5,337) LED106.1@177.5,338.25 ; v2(180,337) LED112.1@180,338.25 ; v2(183.75,256.25) C6.1@185,256.25 ; C7.1@192.5,231.25 v2(192.5,232.5) ; v2(205.15,231.345) 205.175,231.32 U7.1@207.25,231.32 ; v2(205.15,242.775) 205.175,242.75 U7.10@207.25,242.75 ; U4.10@232.75,235 234.825,235 v2(234.85,234.975) ; U4.1@232.75,246.43 232.88,246.3 v2(235.1,246.3) ; U4.19@242.25,245.16 244.29,245.16 v2(244.325,245.125) ; LED15.1@247.5,221 v2(247.5,222.25) ; C4.1@247.5,246.5 v2(248.75,246.5) ; LED9.1@250,221 v2(250,222.25) ; LED52.1@252.5,221 v2(252.5,222.25) ; LED46.1@255,221 v2(255,222.25) ; LED40.1@257.5,221 v2(257.5,222.25) ; LED33.1@260,221 v2(260,222.25) ; LED27.1@262.5,221 v2(262.5,222.25) ; LED21.1@265,221 v2(265,222.25) ; LED14.1@267.5,221 v2(267.5,222.25) ; LED8.1@270,221 v2(270,222.25) ; LED65.1@296.5,196.5 v2(297.75,196.5) ; LED71.1@296.5,199 v2(297.75,199) ; LED77.1@296.5,201.5 v2(297.75,201.5) ; LED84.1@296.5,204 v2(297.75,204) ; LED90.1@296.5,206.5 v2(297.75,206.5) ; LED96.1@296.5,209 v2(297.75,209) ; LED103.1@296.5,211.5 v2(297.75,211.5) ; LED109.1@296.5,214 v2(297.75,214) ; LED66.1@296.5,216.5 v2(298.5,216.5) ; LED72.1@296.5,219 297.75,219 298.658,219.908 v2(298.658,221.161) ; LED78.1@296.5,221.5 297.4,222.4 v2(298.2,222.4) ; LED85.1@296.5,224 v2(297.75,224) ; LED91.1@296.5,226.5 v2(297.75,226.5) ; LED97.1@296.5,229 v2(297.75,229) ; LED104.1@296.5,231.5 v2(297.75,231.5) ; v2(306.921,198) C10.1@308.171,198 ; v2(306.921,218) C11.1@308.171,218 ; v2(390.5,288.5) LED83.1@391.75,288.5 ; v2(390.5,291) LED76.1@391.75,291 ; v2(390.5,293.5) LED70.1@391.75,293.5 ; v2(390.5,296) LED64.1@391.75,296 ; v2(390.5,298.5) LED107.1@391.75,298.5 ; v2(390.5,301) LED101.1@391.75,301 ; v2(390.5,303.5) LED94.1@391.75,303.5 ; v2(390.5,306) LED88.1@391.75,306 ; v2(390.5,308.5) LED82.1@391.75,308.5 ; v2(390.5,311) LED75.1@391.75,311
  Top Layer w0.254: v1@136.224,255.634 136.295,255.705 v1(136.414,255.705) ; U15.10@366.75,288.25 v3(369.75,288.25)
  Top Layer w0.508: v3(7.62,228.905) F3.3@7.62,230.502 ; v3(70,169.776) U3.10@70,171.5 ; U3.19@80.16,162 v3(80.16,163.68) ; v3(81.43,169.695) U3.1@81.43,171.5 ; v3(90.075,169.831) U2.10@90.075,171.625 ; U2.19@100.235,162.125 v3(100.235,163.989) ; v3(101.505,169.831) U2.1@101.505,171.625 ; v3(110.49,169.418) 110.573,169.501 U5.10@110.573,171.6 ; U5.19@120.733,162.1 v3(120.733,163.913) ; v3(120.782,156.85) C5.1@122.073,156.85 v3(123.322,156.85) ; U5.1@122.003,171.6 122.003,169.081 v3(122.682,168.402) ; U18.1@144.25,313.75 v3(144.25,315.7) ; v3(145.52,321.542) U18.19@145.52,323.25 ; U18.10@155.68,313.75 v3(155.68,315.617) ; U19.1@165,313.5 v3(165,315.314) ; v3(166.27,321.21) U19.19@166.27,323 ; U6.19@190.25,257.59 v3(192.058,257.59) ; U7.19@197.75,232.59 v3(199.845,232.59) ; v3(197.9,256.32) U6.1@199.75,256.32 ; v3(197.9,267.75) U6.10@199.75,267.75 ; J30.3@286.418,115.56 P515.1@291.338,115.56 ; J29.3@286.418,125.56 P514.1@291.338,125.56 ; J34.3@286.418,135.56 P513.1@291.338,135.56 ; J33.3@286.418,145.56 P512.1@291.338,145.56 ; U16.19@313.421,199.34 v3(315.214,199.34) ; U17.19@313.421,219.34 v3@315.214,219.34 ; v3@320.929,218.07 U17.1@322.921,218.07 ; v3(321.133,209.5) U16.10@322.921,209.5 ; v3(321.183,198.07) U16.1@322.921,198.07 ; v3(321.194,229.5) U17.10@322.921,229.5 ; U14.10@366.75,301.75 U15.1@366.75,299.68 v3(369.75,299.68) 371.02,298.41 U15.19@376.25,298.41 ; U14.1@366.75,313.18 372.287,313.18 v3(372.92,312.547) 373.557,311.91 U14.19@376.25,311.91 ; LED81.2@368.803,9.165 LED61.2@368.803,11.785 LED100.2@368.803,14.245 LED62.2@368.803,16.825 LED60.2@368.803,19.445 LED59.2@368.803,21.865 LED58.2@368.803,24.605 LED57.2@368.803,27.185 LED56.2@368.803,29.765 LED37.2@368.803,32.025 LED18.2@368.803,34.525 LED5.2@368.803,37.105 LED4.2@368.803,39.685 LED3.2@368.803,42.265 LED2.2@368.803,49.965 LED1.2@368.803,52.585 368.803,59.595 P500.1@368.944,59.736 ; C8.1@381.25,313 382.198,313 v4(382.778,312.42) ; C9.1@381.284,299.466 v4(383.286,299.466)
  Top Layer w0.762: v4(6.741,178.15) F2.3@8.25,178.15 ; v4(8.667,201.051) F4.3@8.667,202.56 ; v4(10,78.5) F98.3@10,80 ; v4(14.361,199.994) C1.1@15.87,199.994 ; v4(16.097,52.94) F1.3@16.097,55.94 ; F5.3@19,170.6 v4(20.451,170.6) ; F6.3@19.049,147.036 v4(20.5,147.036) ; v4(405.501,242.494) F14.3@407.01,242.494 ; v4(405.526,262.966) F10.3@407.772,262.966 ; v4(405.641,80.15) F13.3@407.15,80.15 ; v4(405.641,142.65) F8.3@407.15,142.65 ; v4(405.641,313.15) F7.3@407.15,313.15 ; v4(408,331.491) F9.3@408,333 ; F12.3@410,104.5 v4(411.509,104.5) ; F11.3@410,167 v4(411.509,167)
  Top Layer w1.524: pad.1@25.019,2.794 25.035,3.318 F20.3@25.035,7.53 ; pad.1@78.359,2.413 78.375,3.318 F16.3@78.375,7.53 ; F18.3@110.823,11.52 115.035,11.52 pad.1@115.926,11.506 ; F15.3@164.417,11.52 168.629,11.52 pad.1@168.645,11.504 ; F19.3@218.011,11.52 222.223,11.52 pad.1@222.239,11.504 ; F17.3@271.605,11.52 275.817,11.52 pad.1@275.833,11.504
  Bottom Layer w0.508: v3@122.555,168.529 v3(122.682,168.402)
  other v1: 304.507,34.15 307.047,34.15 309.587,34.15 312.127,34.15 314.667,34.15 317.207,34.15 319.747,34.15 322.287,34.15 324.827,34.15 327.367,34.15 329.907,34.15 332.447,34.15 253.191,34.384 255.731,34.384 258.271,34.384 260.811,34.384 263.351,34.384 265.891,34.384 268.431,34.384 270.971,34.384 273.511,34.384 276.051,34.384 278.591,34.384 281.131,34.384 69.219,37.346 71.759,37.346 74.299,37.346 76.839,37.346 79.379,37.346 81.919,37.346 84.459,37.346 86.999,37.346 92.079,37.346 94.619,37.346 97.159,37.346 99.699,37.346 102.239,37.346 104.779,37.346 107.319,37.346 109.859,37.346 114.939,37.346 117.479,37.346 120.019,37.346 122.559,37.346 125.099,37.346 127.639,37.346 130.179,37.346 132.719,37.346 137.799,37.346 140.339,37.346 142.879,37.346 145.419,37.346 147.959,37.346 150.499,37.346 153.039,37.346 155.579,37.346 160.659,37.346 163.199,37.346 165.739,37.346 168.279,37.346 170.819,37.346 173.359,37.346 175.899,37.346 178.439,37.346 183.519,37.346 186.059,37.346 188.599,37.346 191.139,37.346 193.679,37.346 196.219,37.346 198.759,37.346 201.299,37.346 222.889,58.936 222.889,61.476 222.889,64.016 222.889,66.556 222.889,69.096 36.961,70.112 222.889,71.636 36.961,72.652 222.889,74.176 36.961,75.192 366.404,76.246 368.944,76.246 371.484,76.246 374.024,76.246 376.564,76.246 379.104,76.246 381.644,76.246 384.184,76.246 222.889,76.716 36.961,77.732 222.889,79.256 36.961,80.272 222.889,81.796 36.961,82.812 222.889,84.336 222.889,86.876 265.524,87.423 301.07,87.47 303.61,87.47 306.15,87.47 308.69,87.47 311.23,87.47 313.77,87.47 222.889,89.416 265.524,89.963 222.889,91.956 265.524,92.503 222.889,94.496 265.524,95.043 36.961,96.02 222.889,97.036 265.524,97.583 36.961,98.56 222.889,99.576 265.524,100.123 36.961,101.1 222.889,102.116 36.961,103.64 222.889,104.656 36.961,106.18 222.889,107.196 36.961,108.72 222.889,109.736 36.961,111.26 222.889,112.276 307.928,113.14 36.961,113.8 222.889,114.816 307.928,115.64 36.961,116.34 222.889,117.356 307.928,118.14 36.961,118.88 222.889,119.896 307.928,120.64 36.961,121.42 244.682,122.268 247.222,122.268 249.762,122.268 252.302,122.268 254.842,122.268 257.382,122.268 259.922,122.268 262.462,122.268 222.889,122.436 307.928,123.14 36.961,123.96 307.928,125.64 36.961,126.5 307.928,128.14 36.961,129.04 307.928,130.64 361.324,131.142 363.864,131.142 366.404,131.142 368.944,131.142 371.484,131.142 374.024,131.142 376.564,131.142 379.104,131.142 381.644,131.142 384.184,131.142 36.961,131.58 307.928,133.14 346.92,133.783 349.46,133.783 36.961,134.12 307.928,135.64 307.928,138.14 307.928,140.64 307.928,143.14 307.928,145.64 307.928,148.14 307.928,150.64 182.198,157.59 182.198,160.13 182.198,162.67 182.198,165.21 222.219,167.226 224.759,167.226 182.198,167.75 182.198,170.29 182.198,172.83 182.198,175.37 283.798,177.275 286.338,177.275 288.878,177.275 291.418,177.275 293.958,177.275 296.498,177.275 299.038,177.275 301.578,177.275 304.118,177.275 306.658,177.275 309.198,177.275 311.738,177.275 314.278,177.275 316.818,177.275 319.358,177.275 321.898,177.275 324.438,177.275 326.978,177.275 329.518,177.275 332.058,177.275 334.598,177.275 337.138,177.275 339.678,177.275 342.218,177.275 344.758,177.275 347.298,177.275 349.838,177.275 352.378,177.275 354.918,177.275 357.458,177.275 359.998,177.275 362.538,177.275 365.078,177.275 367.618,177.275 370.158,177.275 372.698,177.275 375.238,177.275 377.778,177.275 380.318,177.275 382.858,177.275 385.398,177.275 387.938,177.275 390.478,177.275 393.018,177.275 395.558,177.275 398.098,177.275 182.198,177.91 239.348,177.91 241.888,177.91 244.428,177.91 246.968,177.91 249.508,177.91 252.048,177.91 254.588,177.91 257.128,177.91 259.668,177.91 262.208,177.91 31.439,178.43 33.979,178.43 36.519,178.43 39.059,178.43 182.198,180.45 136.224,181.974 182.198,182.99 136.224,184.514 182.198,185.53 31.439,186.05 33.979,186.05 36.519,186.05 39.059,186.05 136.224,187.054 182.198,188.07 136.224,189.594 182.198,190.61 136.224,192.134 182.198,193.15 136.224,194.674 182.198,195.69 37.164,207.374 136.224,207.374 37.164,209.914 136.224,209.914 394.288,211.565 37.164,212.454 136.224,212.454 394.288,214.105 37.164,214.994 136.224,214.994 394.288,216.645 37.164,217.534 136.224,217.534 394.288,219.185 37.164,220.074 136.224,220.074 394.288,221.725 37.164,222.614 136.224,222.614 205.59,223.502 208.13,223.502 210.67,223.502 213.21,223.502 215.75,223.502 218.29,223.502 220.83,223.502 223.37,223.502 225.91,223.502 228.45,223.502 230.99,223.502 233.53,223.502 236.07,223.502 238.61,223.502 241.15,223.502 243.69,223.502 394.288,224.265 37.164,225.154 136.224,225.154 394.288,226.805 37.164,227.694 136.224,227.694 394.288,229.345 37.164,230.234 136.224,230.234 394.288,231.885 37.164,232.774 136.224,232.774 394.288,234.425 37.164,235.314 136.224,235.314 37.164,237.854 136.224,237.854 37.164,240.394 136.224,240.394 37.164,242.934 136.224,242.934 37.164,245.474 136.224,245.474 37.164,248.014 136.224,248.014 37.164,250.554 136.224,250.554 283.798,250.935 286.338,250.935 288.878,250.935 291.418,250.935 293.958,250.935 296.498,250.935 299.038,250.935 301.578,250.935 304.118,250.935 306.658,250.935 309.198,250.935 311.738,250.935 314.278,250.935 316.818,250.935 319.358,250.935 321.898,250.935 324.438,250.935 326.978,250.935 329.518,250.935 332.058,250.935 334.598,250.935 337.138,250.935 339.678,250.935 342.218,250.935 344.758,250.935 347.298,250.935 349.838,250.935 352.378,250.935 354.918,250.935 357.458,250.935 359.998,250.935 362.538,250.935 365.078,250.935 367.618,250.935 370.158,250.935 372.698,250.935 375.238,250.935 377.778,250.935 380.318,250.935 382.858,250.935 385.398,250.935 387.938,250.935 390.478,250.935 393.018,250.935 395.558,250.935 398.098,250.935 37.164,253.094 136.224,253.094 37.164,255.634 37.164,258.174 136.224,258.174 37.164,260.714 136.224,260.714 37.164,263.254 136.224,263.254 37.164,265.794 136.224,265.794 37.164,268.334 136.224,268.334 37.164,270.874 136.224,270.874 37.164,273.414 136.224,273.414 37.164,275.954 136.224,275.954 37.164,278.494 136.224,278.494 37.164,281.034 136.224,281.034 37.164,283.574 136.224,283.574 173.332,285.732 37.164,286.114 136.224,286.114 173.332,288.272 269.852,288.272 37.164,288.654 136.224,288.654 173.332,290.812 269.852,290.812 37.164,291.194 136.224,291.194 173.332,293.352 269.852,293.352 37.164,293.734 136.224,293.734 173.332,295.892 269.852,295.892 37.164,296.274 136.224,296.274 173.332,298.432 269.852,298.432 37.164,298.814 136.224,298.814 173.332,300.972 269.852,300.972 37.164,301.354 136.224,301.354 173.332,303.512 269.852,303.512 37.164,303.894 136.224,303.894 269.852,306.052 37.164,306.434 136.224,306.434 203.542,315.958 206.082,315.958 208.622,315.958 211.162,315.958 213.702,315.958 216.242,315.958 218.782,315.958 221.322,315.958 223.862,315.958 226.402,315.958 228.942,315.958 231.482,315.958 234.022,315.958 236.562,315.958 239.102,315.958 241.642,315.958 38.434,317.864 40.974,317.864 43.514,317.864 46.054,317.864 48.594,317.864 51.134,317.864 53.674,317.864 56.214,317.864 58.754,317.864 61.294,317.864 63.834,317.864 66.374,317.864 68.914,317.864 71.454,317.864 73.994,317.864 76.534,317.864 79.074,317.864 81.614,317.864 84.154,317.864 86.694,317.864 89.234,317.864 91.774,317.864 94.314,317.864 96.854,317.864 99.394,317.864 101.934,317.864 104.474,317.864 107.014,317.864 109.554,317.864 112.094,317.864 114.634,317.864 117.174,317.864 119.714,317.864 122.254,317.864 124.794,317.864 127.334,317.864 129.874,317.864 132.414,317.864 134.954,317.864 137.494,317.864 290.428,327.02 292.968,327.02 295.508,327.02 298.048,327.02 300.588,327.02 303.128,327.02 305.668,327.02 308.208,327.02 310.748,327.02 313.288,327.02 315.828,327.02 318.368,327.02 320.908,327.02 323.448,327.02 325.988,327.02 328.528,327.02 331.068,327.02 333.608,327.02 336.148,327.02 338.688,327.02 341.228,327.02 343.768,327.02 346.308,327.02 348.848,327.02 351.388,327.02 353.928,327.02 356.468,327.02 359.008,327.02 361.548,327.02 364.088,327.02 366.628,327.02 369.168,327.02 371.708,327.02 374.248,327.02
  other v2: 65.75,149.127 68.25,149.127 70.75,149.127 73.25,149.127 75.75,149.127 78.25,149.127 80.75,149.127 83.25,149.127 85.75,149.127 88.25,149.127 90.75,149.127 93.25,149.127 95.75,149.127 98.25,149.127 100.75,149.127 103.25,149.127 105.75,149.127 108.25,149.127 110.75,149.127 113.25,149.127 115.75,149.127 118.25,149.127 120.75,149.127 123.25,149.127
  other v3: 320.929,218.059 315.214,219.329
  other v4: 16.129,53.848
I2C0_SCL: P204.1 P410.1 P438.1 P444.1 R6.2 U5.5 | length 610.2
  Top Layer w0.152: U5.5@116.923,171.6 116.923,168.402 118.523,166.802 155.52,166.802 155.655,166.667 v2(155.655,166.624)
  Top Layer w0.254: v1@155.655,64.84 v1(155.655,67.888) ; P444.1@268.431,17.874 269.557,19 282,19 283,20 283,28 R6.2@285,30
  Bottom Layer w0.254: P410.1@20.451,118.88 17.606,116.036 17.606,68.003 20.769,64.84 198.304,64.84 248.666,14.478 265.035,14.478 ; P204.1@152.734,212.454 155.655,209.533 v1(155.655,67.888) ; P444.1@268.431,17.874 265.035,14.478 ; P438.1@319.747,17.64 321.206,19.099 323.189,19.099 323.676,18.612 323.676,17.088 321.066,14.478 265.035,14.478
  other v1: 155.702,65.024
I2C0_SDA: P226.1 P409.1 P437.1 P443.1 R5.2 U5.4 | length 564.4
  Top Layer w0.152: U5.4@118.193,171.6 118.193,168.402 119.463,167.132 150.749,167.132 154.051,167.132 v2(154.432,167.513)
  Top Layer w0.254: R5.2@285,27.5 285,23.252 v1(289.132,19.12) 291.065,19.12 291.465,18.72 v1(293.088,18.72)
  Bottom Layer w0.254: P409.1@20.451,113.8 18.063,111.413 18.063,68.193 19.892,66.364 154.432,66.364 ; P226.1@152.734,209.914 154.432,208.216 154.432,66.364 ; v1(289.132,19.12) 267.137,19.12 P443.1@265.891,17.874 263.257,15.24 248.793,15.24 197.669,66.364 154.432,66.364 ; v1(293.088,18.72) 315.114,18.72 316.194,17.64 P437.1@317.207,17.64
I2C1_SCL: J11.2 P17.1 P200.1 P211.1 R4.2 U5.7 | length 813.6
  Top Layer w0.152: U5.7@114.383,171.6 114.351,171.632 114.351,187.335 125.72,198.704 149.606,198.704 158.75,207.848 v3@158.75,247.84
  Top Layer w0.254: J11.2@8.5,240.92 8.5,240.347 9.58,239.267 9.58,237.3 10.414,236.466 R4.2@10.414,232.877 ; P211.1@152.734,248.014 159.044,248.014 v3@159.084,247.974 ; v3(238.252,272.44) 239.319,272.44 v3(243.789,276.911)
  Bottom Layer w0.254: P200.1@15.443,269.556 14.3,268.413 14.3,248.375 11.379,245.454 11.379,243.799 J11.2@8.5,240.92 7.163,240.92 2.946,245.136 2.946,316.216 27.635,340.904 98.884,340.904 99.134,341.154 237.291,341.154 245.897,332.548 245.897,279.127 243.789,277.019 v3(243.789,276.911) 290.2,230.5 355.006,230.5 358.55,234.044 358.55,265.34 357.458,266.433 P17.1@357.458,267.445 ; v3(158.576,247.974) 159.152,248.55 205.35,248.55 229.24,272.44 v3(238.252,272.44)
